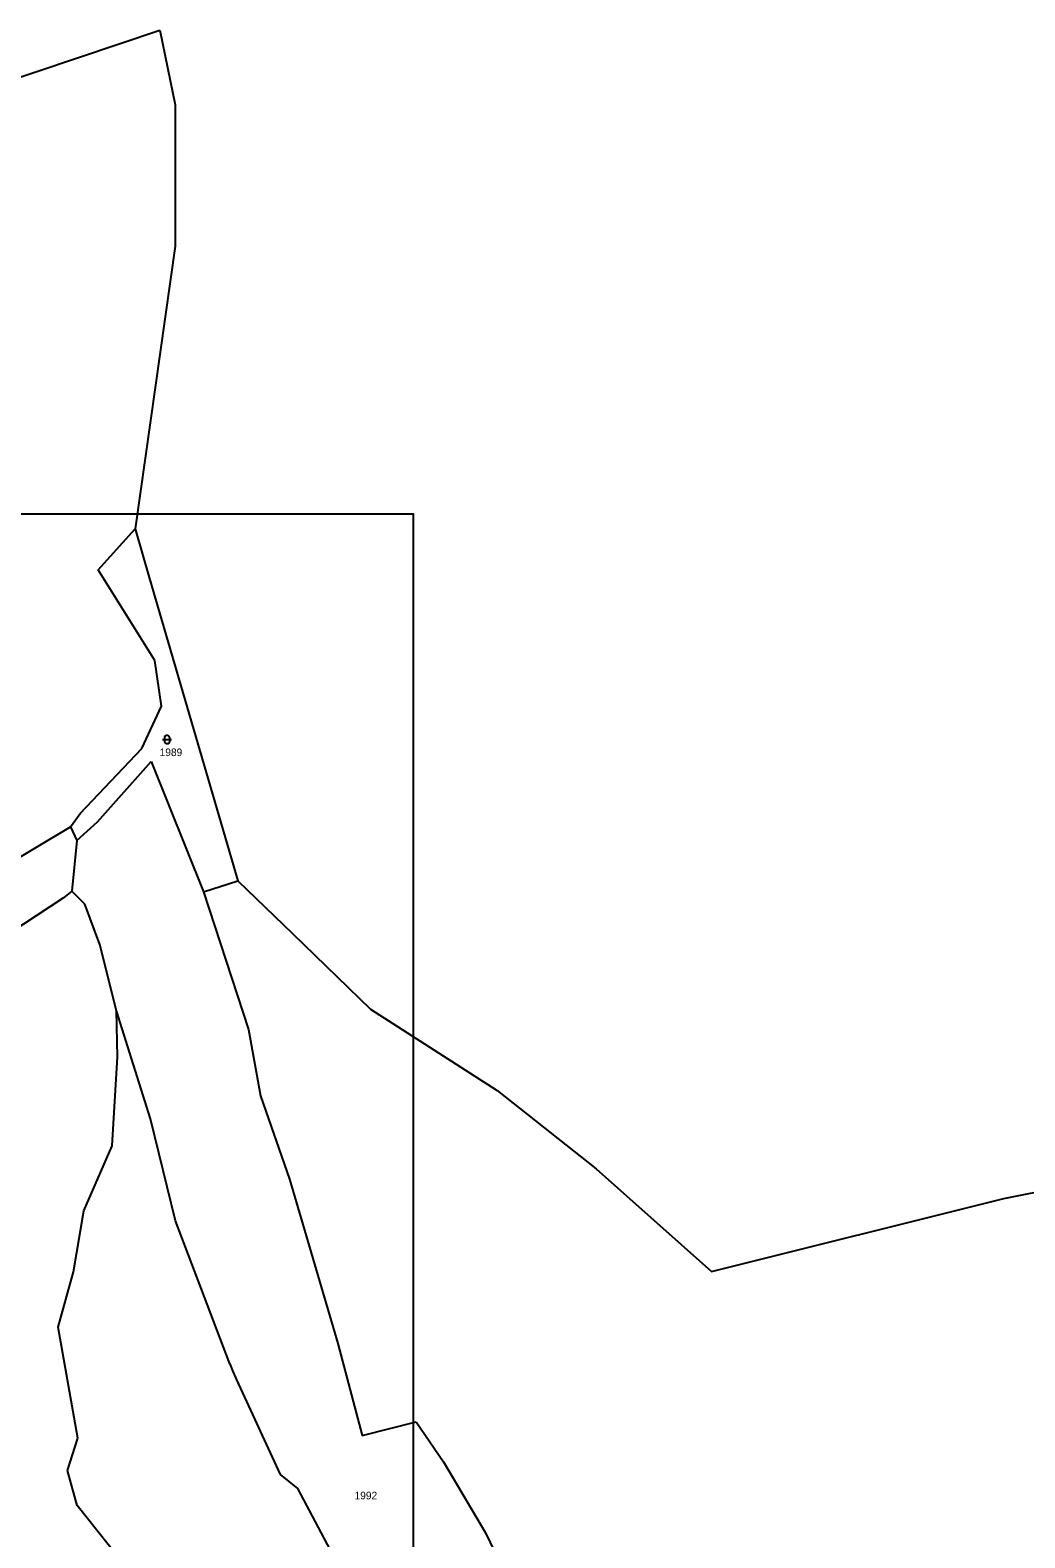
# Model space of a CAD drawing. Extents: x -802857 to -799647, y -1020285 to -1015884.
# Drawn here: x -800948.7 to -800726, y -1017248.9 to -1016911.3 of the extents above; entities that cross this region are included whole.
import ezdxf

# ---------------------------------------------------------------- set-up
doc = ezdxf.new("R2010")
doc.units = 0
for name, color, linetype in [('Default', 7, 'Continuous'), ('KN_HRANICE', 7, 'Continuous'), ('KN_KULTURY', 7, 'Continuous'), ('KN_PARCELY', 7, 'Continuous'), ('LEGENDA', 7, 'Continuous')]:
    doc.layers.add(name, color=color, linetype=linetype)

# ---------------------------------------------------------------- blocks, each defined once
blk = doc.blocks.new('316')
at = {"layer": 'Default'}
for points in [[(-1, 1), (0.27, 1), (1, 1)], [(-0.5, 1.5), (-0.4, 1.79), (-0.15, 1.97), (0.16, 1.97), (0.41, 1.79), (0.51, 1.5), (0.51, 0.5), (0.41, 0.21), (0.16, 0.03), (-0.15, 0.03), (-0.4, 0.21), (-0.5, 0.5), (-0.5, 1.5)]]:
    blk.add_lwpolyline(points, dxfattribs=at)

msp = doc.modelspace()

# ---------------------------------------------------------------- linework, layer by layer
at = {"layer": 'KN_HRANICE'}
for p, q in [((-800966.67, -1016927.02), (-800919.72, -1016911.28)), ((-800919.72, -1016911.28), (-800916.22, -1016927.99)), ((-800916.22, -1016927.99), (-800916.27, -1016959.63)), ((-800916.27, -1016959.63), (-800925.21, -1017022.97)), ((-800933.53, -1017032.14), (-800925.21, -1017022.97)), ((-800925.21, -1017022.97), (-800922.04, -1017033.85)), ((-800920.82, -1017052.46), (-800933.53, -1017032.14)), ((-800922.04, -1017033.85), (-800902.21, -1017101.81)), ((-800919.32, -1017062.66), (-800920.82, -1017052.46)), ((-800923.75, -1017072.16), (-800919.32, -1017062.66)), ((-800937.55, -1017086.7), (-800923.75, -1017072.16)), ((-800933.62, -1017088.6), (-800921.62, -1017075.06)), ((-800921.62, -1017075.06), (-800909.89, -1017104.24)), ((-800939.68, -1017089.67), (-800937.55, -1017086.7)), ((-800954.55, -1017098.59), (-800939.68, -1017089.67)), ((-800939.68, -1017089.67), (-800938.24, -1017092.74)), ((-800938.24, -1017092.74), (-800933.62, -1017088.6)), ((-800938.24, -1017092.74), (-800939.36, -1017104.09)), ((-800939.36, -1017104.09), (-800941.26, -1017105.59)), ((-800936.45, -1017107.04), (-800939.36, -1017104.09)), ((-800909.89, -1017104.24), (-800902.21, -1017101.81)), ((-800909.89, -1017104.24), (-800899.86, -1017135.06)), ((-800902.21, -1017101.81), (-800889.98, -1017113.62)), ((-800941.26, -1017105.59), (-801001.86, -1017145.37)), ((-800933.11, -1017116.01), (-800936.45, -1017107.04)), ((-800889.98, -1017113.62), (-800872.5, -1017130.51)), ((-800929.36, -1017130.92), (-800933.11, -1017116.01)), ((-800921.75, -1017155.11), (-800929.36, -1017130.92)), ((-800929.15, -1017141.22), (-800929.36, -1017130.92)), ((-800872.5, -1017130.51), (-800844.16, -1017148.71)), ((-800899.86, -1017135.06), (-800897.14, -1017149.92)), ((-800930.37, -1017161.16), (-800929.15, -1017141.22)), ((-800844.16, -1017148.71), (-800821.95, -1017166.27)), ((-800897.14, -1017149.92), (-800890.63, -1017168.58)), ((-800916.2, -1017177.92), (-800921.75, -1017155.11)), ((-800730.67, -1017172.91), (-800655.34, -1017157.94)), ((-800936.68, -1017175.71), (-800930.37, -1017161.16)), ((-800890.63, -1017168.58), (-800879.8, -1017205.42)), ((-800821.95, -1017166.27), (-800796.12, -1017189.28)), ((-800939.01, -1017189.32), (-800936.68, -1017175.71)), ((-800796.12, -1017189.28), (-800730.67, -1017172.91)), ((-800904.03, -1017209.93), (-800916.2, -1017177.92)), ((-800942.43, -1017201.78), (-800939.01, -1017189.32)), ((-800938.06, -1017226.62), (-800942.43, -1017201.78)), ((-800879.8, -1017205.42), (-800874.4, -1017226.03)), ((-800904.03, -1017209.93), (-800903.5, -1017211.33)), ((-800903.5, -1017211.33), (-800902.5, -1017213.51)), ((-800902.5, -1017213.51), (-800892.76, -1017234.71)), ((-800874.4, -1017226.03), (-800862.25, -1017222.93)), ((-800862.25, -1017222.93), (-800856.18, -1017231.88)), ((-800940.38, -1017233.81), (-800938.06, -1017226.62)), ((-800856.18, -1017231.88), (-800846.78, -1017247.77)), ((-800938.23, -1017241.65), (-800940.38, -1017233.81)), ((-800892.76, -1017234.71), (-800888.89, -1017237.87)), ((-800888.89, -1017237.87), (-800861.07, -1017290.03)), ((-800925.53, -1017257.6), (-800938.23, -1017241.65)), ((-800846.78, -1017247.77), (-800839.54, -1017262.75))]:
    msp.add_line(p, q, dxfattribs=at)
at = {"layer": 'LEGENDA'}
msp.add_lwpolyline([(-801703.84, -1017613.71), (-800862.84, -1017613.71), (-800862.84, -1017019.71), (-801703.84, -1017019.71)], close=True, dxfattribs=at)

# ---------------------------------------------------------------- block references
at = {"layer": 'KN_KULTURY'}
msp.add_blockref('316', (-800918.06, -1017071.15), dxfattribs=at)

# ---------------------------------------------------------------- texts
at = {"layer": 'KN_PARCELY'}
for s, p in [('1989', (-800919.72, -1017073.85)), ('1992', (-800876.07, -1017240.3))]:
    msp.add_text(s, height=1.7, dxfattribs=at).set_placement(p)

doc.saveas('drawing.dxf')
